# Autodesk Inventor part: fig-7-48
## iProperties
Shininess: 77.0
Length Units: 11269
Angle Units: 11279
Time Units: 11290
Mass Units: 11283
Length Display Precision: 3
Angle Display Precision: 2
Created: 2002-01
Part Number: fig-7-48
Document SubType Name: Modeling
Designer: ***
Density: 0.0
Volumn: 0.0
Area: 0.0
PropertySet Name: Model Information
Control State: 0
Master: False
Checked Out: False
Author: ***
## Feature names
1. Extrusion1
2. Shell3
